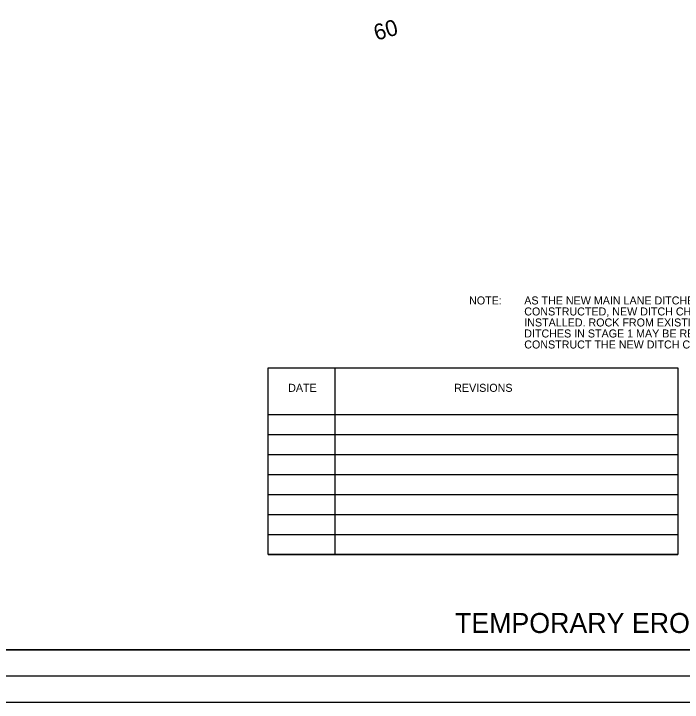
# Model space of a CAD drawing. Extents: x 9844 to 14104, y 9961 to 11067.
# Drawn here: x 10793 to 11294, y 9961 to 10477 of the extents above; entities that cross this region are included whole.
import ezdxf

# ---------------------------------------------------------------- set-up
doc = ezdxf.new("R2010")
doc.units = 0
for name, color, linetype in [('R_Border', 7, 'Continuous'), ('R_Border Notes', 7, 'Continuous'), ('R_Detour Annot', 7, 'Continuous'), ('R_Horz Alg Curve Annot', 7, 'Continuous'), ('R_No Plot', 7, 'Continuous'), ('R_NoPlot', 7, 'Continuous'), ('TEXT', 7, 'Continuous')]:
    doc.layers.add(name, color=color, linetype=linetype)

msp = doc.modelspace()

# ---------------------------------------------------------------- linework, layer by layer
at = {"layer": 'R_Border'}
for p, q in [((11580.9, 10000), (10000, 10000)), ((9843.9, 9960.6), (11603.9, 9960.6))]:
    msp.add_line(p, q, dxfattribs=at)
at = {"layer": 'R_Border Notes'}
for p, q in [((11033.7, 10211.28), (11033.7, 10071.28)), ((11033.7, 10211.28), (11290.72, 10211.28)), ((10983.7, 10176.28), (11290.72, 10176.28)), ((10983.7, 10161.28), (11290.72, 10161.28)), ((10983.7, 10146.28), (11290.72, 10146.28)), ((10983.7, 10131.28), (11290.72, 10131.28)), ((10983.7, 10116.28), (11290.72, 10116.28)), ((10983.7, 10101.28), (11290.72, 10101.28)), ((10983.7, 10086.28), (11290.72, 10086.28)), ((10983.7, 10071.28), (11290.72, 10071.28))]:
    msp.add_line(p, q, dxfattribs=at)
msp.add_lwpolyline([(10983.7, 10211.28), (11290.72, 10211.28), (11290.72, 10071.28), (10983.7, 10071.28)], close=True, dxfattribs=at)
at = {"layer": 'R_No Plot'}
msp.add_lwpolyline([(10000, 10000), (11580.9, 10000), (11580.3, 10963.3), (11365.4, 10963.3), (11357.31, 10959.87), (11348.49, 10961.4), (11348.26, 10977.9), (11169.6, 10977.9), (11169.6, 11027.3), (10000, 11027.3)], close=True, dxfattribs=at)
msp.add_lwpolyline([(10000, 10000), (11580.9, 10000), (11580.3, 10963.3), (11365.4, 10963.3), (11357.31, 10959.87), (11348.49, 10961.4), (11348.26, 10977.9), (11169.6, 10977.9), (11169.6, 11027.3), (10000, 11027.3)], close=True, dxfattribs=at)
at = {"layer": 'R_NoPlot'}
msp.add_lwpolyline([(9937.96, 11046.77), (11604.66, 11046.77), (11604.66, 9980.09), (9937.96, 9980.09)], close=True, dxfattribs=at)

# ---------------------------------------------------------------- texts
at = {"layer": 'R_Border'}
msp.add_text('TEMPORARY EROSION CONTROL DETAILS', height=15, dxfattribs=at).set_placement((11123.73, 10012.5))
at = {"layer": 'R_Detour Annot'}
msp.add_text('60', height=12, rotation=16.1937, dxfattribs=at).set_placement((11064.85, 10456.4))
at = {"layer": 'R_Horz Alg Curve Annot'}
for s, p in [('DATE', (10998.7, 10193.28)), ('  REVISIONS', (11118.7, 10193.28))]:
    msp.add_text(s, height=6, dxfattribs=at).set_placement(p)
at = {"layer": 'TEXT'}
for s, p in [('NOTE:', (11134.31, 10258.78)), ('AS THE NEW MAIN LANE DITCHES ARE ', (11175.66, 10258.78)), ('CONSTRUCTED, NEW DITCH CHECKS ARE TO BE ', (11175.66, 10250.53)), ('INSTALLED. ROCK FROM EXISTING MAIN LANE ', (11175.66, 10242.28)), ('DITCHES IN STAGE 1 MAY BE REUSED TO ', (11175.66, 10234.03)), ('CONSTRUCT THE NEW DITCH CHECKS.', (11175.66, 10225.78))]:
    msp.add_text(s, height=6, dxfattribs=at).set_placement(p)

doc.saveas('drawing.dxf')
